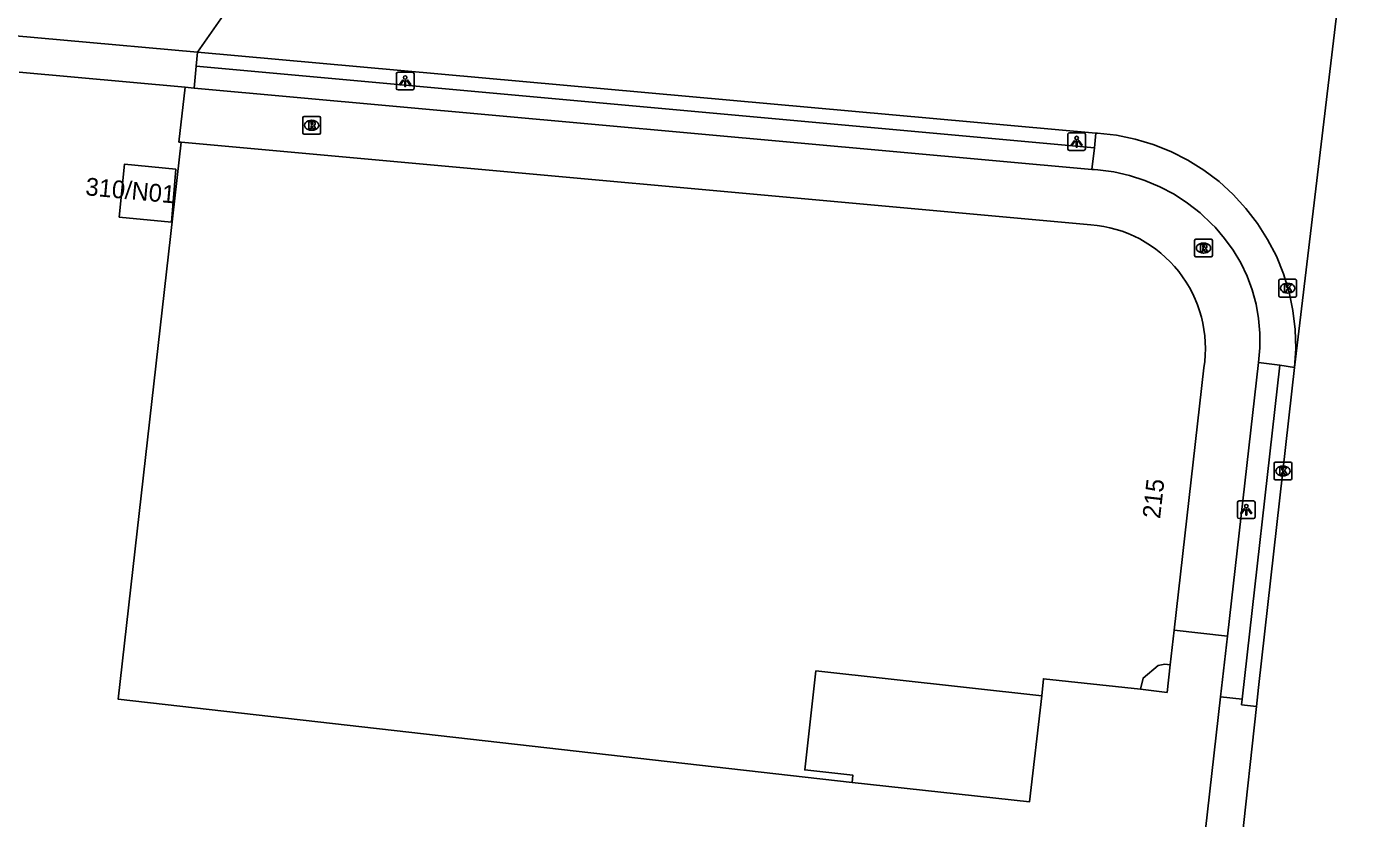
# Model space of a CAD drawing. Extents: x 161389 to 162585, y 388479 to 389761.
# Drawn here: x 162279.1 to 162354.1, y 388816.4 to 388861 of the extents above; entities that cross this region are included whole.
import ezdxf

# ---------------------------------------------------------------- set-up
doc = ezdxf.new("R2010")
doc.units = 0
for name, color, linetype in [('IMGEO_Groenvoorziening', 7, 'Continuous'), ('IMGEO_Kolk', 7, 'Continuous'), ('IMGEO_Lichtpunt', 7, 'Continuous'), ('IMGEO_Pand', 7, 'Continuous'), ('IMGEO_Pand_nummerreeks', 7, 'Continuous'), ('IMGEO_Pand_overbouw', 7, 'Continuous'), ('IMGEO_Rijbaan_lokaal_gesloten', 7, 'Continuous'), ('IMGEO_Rioolput', 7, 'Continuous'), ('IMGEO_Voetpad_open', 7, 'Continuous')]:
    doc.layers.add(name, color=color, linetype=linetype)

msp = doc.modelspace()

# ---------------------------------------------------------------- linework, layer by layer
at = {"layer": 'IMGEO_Groenvoorziening'}
for points in [[(162287.807, 388854.476), (162287.687, 388854.487), (162288.036, 388857.574)], [(162346.766, 388826.65), (162343.766, 388826.99)]]:
    msp.add_lwpolyline(points, dxfattribs=at)
at = {"layer": 'IMGEO_Kolk'}
for p, q in [((162349.656, 388845.833), (162349.656, 388846.685)), ((162349.731, 388846.759), (162350.583, 388846.759)), ((162350.144, 388846.539), (162350.169, 388846.539)), ((162350.657, 388846.685), (162350.657, 388845.833)), ((162350.583, 388845.759), (162349.731, 388845.759)), ((162350.167, 388845.979), (162350.142, 388845.979)), ((162349.39, 388835.533), (162349.39, 388836.385)), ((162349.465, 388836.459), (162350.317, 388836.459)), ((162350.391, 388836.385), (162350.391, 388835.533)), ((162349.901, 388835.679), (162349.876, 388835.679)), ((162349.878, 388836.239), (162349.903, 388836.239)), ((162350.317, 388835.459), (162349.465, 388835.459))]:
    msp.add_line(p, q, dxfattribs=at)
for points in [[(162349.656, 388845.833), (162349.656, 388846.685)], [(162349.731, 388846.759), (162350.583, 388846.759)], [(162349.977, 388846.459), (162350.1, 388846.459), (162350.1, 388846.308), (162350.23, 388846.459), (162350.394, 388846.459), (162350.248, 388846.308), (162350.401, 388846.059), (162350.249, 388846.059), (162350.164, 388846.223), (162350.1, 388846.156), (162350.1, 388846.059), (162349.977, 388846.059), (162349.977, 388846.459)], [(162350.657, 388846.685), (162350.657, 388845.833)], [(162350.583, 388845.759), (162349.731, 388845.759)], [(162349.39, 388835.533), (162349.39, 388836.385)], [(162349.465, 388836.459), (162350.317, 388836.459)], [(162350.391, 388836.385), (162350.391, 388835.533)], [(162349.711, 388836.159), (162349.834, 388836.159), (162349.834, 388836.008), (162349.964, 388836.159), (162350.128, 388836.159), (162349.982, 388836.008), (162350.135, 388835.759), (162349.983, 388835.759), (162349.898, 388835.923), (162349.834, 388835.856), (162349.834, 388835.759), (162349.711, 388835.759), (162349.711, 388836.159)], [(162350.317, 388835.459), (162349.465, 388835.459)]]:
    msp.add_lwpolyline(points, dxfattribs=at)
for centre, start, end in [((162349.733, 388846.683), 91.55205, 178.44795), ((162349.733, 388846.683), 91.55205, 178.44795), ((162350.581, 388846.683), 1.55205, 88.44795), ((162350.581, 388846.683), 1.55205, 88.44795), ((162349.733, 388845.835), 181.55205, 268.44795), ((162349.733, 388845.835), 181.55205, 268.44795), ((162350.581, 388845.835), 271.55205, 358.44795), ((162350.581, 388845.835), 271.55205, 358.44795), ((162349.467, 388836.383), 91.55205, 178.44795), ((162349.467, 388836.383), 91.55205, 178.44795), ((162350.315, 388836.383), 1.55205, 88.44795), ((162350.315, 388836.383), 1.55205, 88.44795), ((162349.467, 388835.535), 181.55205, 268.44795), ((162349.467, 388835.535), 181.55205, 268.44795), ((162350.315, 388835.535), 271.55205, 358.44795), ((162350.315, 388835.535), 271.55205, 358.44795)]:
    msp.add_arc(centre, 0.0765, start, end, dxfattribs=at)
for centre, major_axis, ratio, start_param, end_param in [((162350.143, 388846.259), (-0.387, 0.002), 0.722429, 4.712389, 7.853982), ((162350.168, 388846.259), (-0.39, 0.002), 0.717154, 1.570796, 4.712389), ((162349.877, 388835.959), (-0.387, 0.002), 0.722429, 4.712389, 7.853982), ((162349.902, 388835.959), (-0.39, 0.002), 0.717154, 1.570796, 4.712389)]:
    msp.add_ellipse(centre, major_axis=major_axis, ratio=ratio, start_param=start_param, end_param=end_param, dxfattribs=at)
at = {"layer": 'IMGEO_Lichtpunt'}
for p, q in [((162299.938, 388858.325), (162299.938, 388857.518)), ((162299.938, 388858.325), (162299.938, 388857.518)), ((162300.84, 388858.42), (162300.032, 388858.42)), ((162300.84, 388858.42), (162300.032, 388858.42)), ((162300.934, 388857.518), (162300.934, 388858.325)), ((162300.934, 388857.518), (162300.934, 388858.325)), ((162300.032, 388857.424), (162300.84, 388857.424)), ((162300.032, 388857.424), (162300.84, 388857.424)), ((162337.767, 388854.916), (162337.767, 388854.109)), ((162337.767, 388854.916), (162337.767, 388854.109)), ((162338.669, 388855.011), (162337.861, 388855.011)), ((162338.669, 388855.011), (162337.861, 388855.011)), ((162338.763, 388854.109), (162338.763, 388854.916)), ((162338.763, 388854.109), (162338.763, 388854.916)), ((162337.861, 388854.015), (162338.669, 388854.015)), ((162337.861, 388854.015), (162338.669, 388854.015)), ((162347.326, 388834.183), (162347.326, 388833.376)), ((162347.326, 388834.183), (162347.326, 388833.376)), ((162348.228, 388834.278), (162347.42, 388834.278)), ((162348.228, 388834.278), (162347.42, 388834.278)), ((162348.322, 388833.376), (162348.322, 388834.183)), ((162348.322, 388833.376), (162348.322, 388834.183)), ((162347.42, 388833.282), (162348.228, 388833.282)), ((162347.42, 388833.282), (162348.228, 388833.282))]:
    msp.add_line(p, q, dxfattribs=at)
for points in [[(162300.312, 388857.989), (162300.351, 388857.961), (162300.163, 388857.699), (162300.125, 388857.726), (162300.312, 388857.989)], [(162300.414, 388857.941), (162300.461, 388857.941), (162300.461, 388857.619), (162300.414, 388857.619), (162300.414, 388857.941)], [(162300.524, 388857.961), (162300.562, 388857.988), (162300.749, 388857.726), (162300.71, 388857.698), (162300.524, 388857.961)], [(162338.141, 388854.58), (162338.18, 388854.552), (162337.992, 388854.29), (162337.954, 388854.317), (162338.141, 388854.58)], [(162338.243, 388854.532), (162338.29, 388854.532), (162338.29, 388854.21), (162338.243, 388854.21), (162338.243, 388854.532)], [(162338.353, 388854.552), (162338.391, 388854.579), (162338.578, 388854.317), (162338.539, 388854.289), (162338.353, 388854.552)], [(162347.7, 388833.847), (162347.739, 388833.819), (162347.551, 388833.557), (162347.513, 388833.584), (162347.7, 388833.847)], [(162347.802, 388833.799), (162347.849, 388833.799), (162347.849, 388833.477), (162347.802, 388833.477), (162347.802, 388833.799)], [(162347.912, 388833.819), (162347.95, 388833.846), (162348.137, 388833.584), (162348.098, 388833.556), (162347.912, 388833.819)]]:
    msp.add_lwpolyline(points, dxfattribs=at)
for centre in [(162300.437, 388858.123), (162338.266, 388854.714), (162347.825, 388833.981)]:
    msp.add_circle(centre, 0.0994, dxfattribs=at)
for centre, start, end in [((162300.032, 388858.325), 90, 180), ((162300.032, 388858.325), 90, 180), ((162300.84, 388858.325), 0, 90), ((162300.84, 388858.325), 0, 90), ((162300.032, 388857.518), 180, 270), ((162300.032, 388857.518), 180, 270), ((162300.84, 388857.518), 270, 0), ((162300.84, 388857.518), 270, 360), ((162337.861, 388854.916), 90, 180), ((162337.861, 388854.916), 90, 180), ((162338.669, 388854.916), 0, 90), ((162338.669, 388854.916), 0, 90), ((162337.861, 388854.109), 180, 270), ((162337.861, 388854.109), 180, 270), ((162338.669, 388854.109), 270, 0), ((162338.669, 388854.109), 270, 360), ((162347.42, 388834.183), 90, 180), ((162347.42, 388834.183), 90, 180), ((162348.228, 388834.183), 0, 90), ((162348.228, 388834.183), 0, 90), ((162347.42, 388833.376), 180, 270), ((162347.42, 388833.376), 180, 270), ((162348.228, 388833.376), 270, 0), ((162348.228, 388833.376), 270, 360)]:
    msp.add_arc(centre, 0.0946, start, end, dxfattribs=at)
at = {"layer": 'IMGEO_Pand'}
for points in [[(162343.766, 388826.99), (162343.546, 388825.042), (162343.228, 388825.075), (162342.869, 388824.995), (162342.013, 388824.299), (162341.857, 388823.664), (162336.398, 388824.261), (162336.306, 388823.293), (162323.575, 388824.702), (162322.952, 388819.118), (162325.666, 388818.823), (162325.623, 388818.422), (162284.27, 388823.103), (162287.807, 388854.476)], [(162339.069, 388849.833), (162287.807, 388854.476)], [(162287.271, 388849.977), (162284.326, 388850.264), (162284.615, 388853.236), (162287.513, 388852.954), (162287.271, 388849.977)], [(162343.766, 388826.99), (162345.439, 388841.767)]]:
    msp.add_lwpolyline(points, dxfattribs=at)
msp.add_arc((162338.526, 388842.856), 6.999, 351.05212, 85.54663, dxfattribs=at)
at = {"layer": 'IMGEO_Pand_overbouw'}
for points in [[(162341.857, 388823.664), (162343.362, 388823.486), (162343.546, 388825.042), (162343.228, 388825.075), (162342.869, 388824.995), (162342.013, 388824.299)], [(162336.306, 388823.293), (162323.575, 388824.702), (162322.952, 388819.118), (162325.666, 388818.823), (162325.623, 388818.422), (162335.604, 388817.317)]]:
    msp.add_lwpolyline(points, close=True, dxfattribs=at)
at = {"layer": 'IMGEO_Rijbaan_lokaal_gesloten'}
for points in [[(162350.544, 388841.795), (162354.085, 388871.528)], [(162293.465, 388866.329), (162288.732, 388859.544)], [(162273.651, 388860.898), (162288.732, 388859.544)], [(162288.732, 388859.544), (162339.344, 388854.997)], [(162339.344, 388854.997), (162339.45, 388854.99), (162340.513, 388854.872), (162341.561, 388854.658), (162342.585, 388854.352), (162343.578, 388853.956), (162344.532, 388853.472), (162345.439, 388852.906), (162346.291, 388852.26), (162347.082, 388851.541), (162347.806, 388850.754), (162348.457, 388849.906), (162349.029, 388849.003), (162349.519, 388848.052), (162349.921, 388847.062), (162350.234, 388846.039), (162350.454, 388844.993), (162350.579, 388843.931), (162350.609, 388842.862), (162350.544, 388841.795)], [(162350.544, 388841.795), (162349.892, 388835.959), (162348.515, 388823.765), (162348.397, 388822.686)], [(162348.397, 388822.686), (162347.549, 388814.966), (162346.508, 388805.67), (162345.796, 388799.312)]]:
    msp.add_lwpolyline(points, dxfattribs=at)
at = {"layer": 'IMGEO_Rioolput'}
for p, q in [((162294.67, 388855.007), (162294.67, 388855.859)), ((162294.745, 388855.933), (162295.597, 388855.933)), ((162295.671, 388855.859), (162295.671, 388855.007)), ((162295.181, 388855.153), (162295.156, 388855.153)), ((162295.158, 388855.713), (162295.183, 388855.713)), ((162295.597, 388854.933), (162294.745, 388854.933)), ((162344.914, 388848.093), (162344.914, 388848.945)), ((162344.989, 388849.019), (162345.841, 388849.019)), ((162345.402, 388848.799), (162345.427, 388848.799)), ((162345.915, 388848.945), (162345.915, 388848.093)), ((162345.841, 388848.019), (162344.989, 388848.019)), ((162345.425, 388848.239), (162345.4, 388848.239))]:
    msp.add_line(p, q, dxfattribs=at)
for points in [[(162294.67, 388855.007), (162294.67, 388855.859)], [(162294.745, 388855.933), (162295.597, 388855.933)], [(162295.671, 388855.859), (162295.671, 388855.007)], [(162295.259, 388855.631), (162295.007, 388855.633), (162295.007, 388855.233)], [(162295.007, 388855.233), (162295.131, 388855.233), (162295.131, 388855.395), (162295.142, 388855.395)], [(162295.185, 388855.552), (162295.131, 388855.552), (162295.131, 388855.471)], [(162295.131, 388855.471), (162295.183, 388855.471)], [(162295.189, 388855.366), (162295.26, 388855.233), (162295.4, 388855.233), (162295.335, 388855.359)], [(162295.597, 388854.933), (162294.745, 388854.933)], [(162344.914, 388848.093), (162344.914, 388848.945)], [(162344.989, 388849.019), (162345.841, 388849.019)], [(162345.503, 388848.717), (162345.251, 388848.719), (162345.251, 388848.319)], [(162345.251, 388848.319), (162345.375, 388848.319), (162345.375, 388848.481), (162345.386, 388848.481)], [(162345.429, 388848.638), (162345.375, 388848.638), (162345.375, 388848.557)], [(162345.375, 388848.557), (162345.427, 388848.557)], [(162345.433, 388848.452), (162345.504, 388848.319), (162345.644, 388848.319), (162345.579, 388848.445)], [(162345.915, 388848.945), (162345.915, 388848.093)], [(162345.841, 388848.019), (162344.989, 388848.019)]]:
    msp.add_lwpolyline(points, dxfattribs=at)
for centre, radius, start, end in [((162294.747, 388855.857), 0.0765, 91.55205, 178.44795), ((162294.747, 388855.857), 0.0765, 91.55205, 178.44795), ((162295.595, 388855.857), 0.0765, 1.55205, 88.44795), ((162295.595, 388855.857), 0.0765, 1.55205, 88.44795), ((162295.141, 388855.342), 0.0533, 26.02933, 88.69889), ((162295.167, 388855.66), 0.19, 274.7715, 282.96867), ((162295.191, 388855.456), 0.0964, 77.00612, 93.18647), ((162295.205, 388855.513), 0.0378, 276.66336, 79.67722), ((162295.258, 388855.521), 0.109, 350.36119, 89.41601), ((162295.256, 388855.521), 0.112, 277.58423, 350.98172), ((162295.24, 388855.306), 0.108, 29.51342, 73.79051), ((162294.747, 388855.009), 0.0765, 181.55205, 268.44795), ((162294.747, 388855.009), 0.0765, 181.55205, 268.44795), ((162295.595, 388855.009), 0.0765, 271.55205, 358.44795), ((162295.595, 388855.009), 0.0765, 271.55205, 358.44795), ((162344.991, 388848.943), 0.0765, 91.55205, 178.44795), ((162344.991, 388848.943), 0.0765, 91.55205, 178.44795), ((162345.385, 388848.428), 0.0533, 26.02933, 88.69889), ((162345.411, 388848.746), 0.19, 274.7715, 282.96867), ((162345.435, 388848.542), 0.0964, 77.00612, 93.18647), ((162345.449, 388848.599), 0.0378, 276.66336, 79.67722), ((162345.502, 388848.607), 0.109, 350.36119, 89.41601), ((162345.5, 388848.607), 0.112, 277.58423, 350.98172), ((162345.484, 388848.392), 0.108, 29.51342, 73.79051), ((162345.839, 388848.943), 0.0765, 1.55205, 88.44795), ((162345.839, 388848.943), 0.0765, 1.55205, 88.44795), ((162344.991, 388848.095), 0.0765, 181.55205, 268.44795), ((162344.991, 388848.095), 0.0765, 181.55205, 268.44795), ((162345.839, 388848.095), 0.0765, 271.55205, 358.44795), ((162345.839, 388848.095), 0.0765, 271.55205, 358.44795)]:
    msp.add_arc(centre, radius, start, end, dxfattribs=at)
for centre, major_axis, ratio, start_param, end_param in [((162295.157, 388855.433), (-0.387, 0.002), 0.722429, 4.712389, 7.853982), ((162295.182, 388855.433), (-0.39, 0.002), 0.717154, 1.570796, 4.712389), ((162345.401, 388848.519), (-0.387, 0.002), 0.722429, 4.712389, 7.853982), ((162345.426, 388848.519), (-0.39, 0.002), 0.717154, 1.570796, 4.712389)]:
    msp.add_ellipse(centre, major_axis=major_axis, ratio=ratio, start_param=start_param, end_param=end_param, dxfattribs=at)
at = {"layer": 'IMGEO_Voetpad_open'}
for points in [[(162288.732, 388859.544), (162288.662, 388858.772)], [(162288.036, 388857.574), (162278.689, 388858.42)], [(162288.552, 388857.528), (162288.662, 388858.772)], [(162288.662, 388858.772), (162339.281, 388854.162)], [(162288.552, 388857.528), (162288.036, 388857.574)], [(162339.12, 388852.95), (162288.552, 388857.528)], [(162339.281, 388854.162), (162339.344, 388854.997)], [(162339.12, 388852.95), (162339.281, 388854.162)], [(162348.515, 388842.074), (162348.59, 388842.897), (162348.592, 388843.724), (162348.519, 388844.548), (162348.374, 388845.362), (162348.156, 388846.159), (162347.868, 388846.934), (162347.511, 388847.68), (162347.09, 388848.391), (162346.607, 388849.062), (162346.065, 388849.687), (162345.887, 388849.87), (162345.227, 388850.493), (162344.515, 388851.054), (162343.755, 388851.55), (162342.954, 388851.976), (162342.118, 388852.328), (162341.254, 388852.605), (162340.369, 388852.803), (162339.469, 388852.921), (162339.262, 388852.937), (162339.12, 388852.95)], [(162346.766, 388826.65), (162348.515, 388842.074)], [(162349.725, 388841.919), (162347.59, 388823.099)], [(162349.725, 388841.919), (162348.515, 388842.074)], [(162350.544, 388841.795), (162349.725, 388841.919)], [(162346.379, 388823.232), (162346.766, 388826.65)], [(162344.428, 388805.878), (162344.552, 388807.124), (162346.379, 388823.232)], [(162346.379, 388823.232), (162347.59, 388823.099)], [(162347.59, 388823.099), (162347.556, 388822.796), (162348.397, 388822.686)]]:
    msp.add_lwpolyline(points, dxfattribs=at)

# ---------------------------------------------------------------- texts
at = {"layer": 'IMGEO_Pand_nummerreeks'}
for s, rotation, p in [('310/N01', 354.67725, (162282.392, 388851.5)), ('215', 83.54298, (162342.965, 388833.243))]:
    msp.add_text(s, height=1, rotation=rotation, dxfattribs=at).set_placement(p)

doc.saveas('drawing.dxf')
